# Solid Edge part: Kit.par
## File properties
Author: bmolnar
Last saved by: bmolnar
Revision: 78
Sűrűség: 0,000 kg/m^3
Pontosság: 0,990
Username: bmolnar
Dokumentum tartalom típus: 0
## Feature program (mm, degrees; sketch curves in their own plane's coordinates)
base feature "unnamed BaseFeature 1"
sketch for "unnamed Hole 1" plane through (44.5, 44.5, -94.5) normal (0, 0, -1) x-axis (-1, 0, 0)
  hole centre (0, 0) bore radius 4.188
hole "unnamed Hole 1" through
sketch for "unnamed Hole 2" plane through (44.5, 44.5, -94.5) normal (0, 0, -1) x-axis (-1, 0, 0)
  hole centre (89, 0) bore radius 4.188
hole "unnamed Hole 2" through
sketch for "unnamed Hole 3" plane through (44.5, 44.5, -94.5) normal (0, 0, -1) x-axis (-1, 0, 0)
  hole centre (89, -89) bore radius 4.188
hole "unnamed Hole 3" through
sketch for "unnamed Hole 4" plane through (44.5, 44.5, -94.5) normal (0, 0, -1) x-axis (-1, 0, 0)
  hole centre (0, -89) bore radius 4.188
hole "unnamed Hole 4" through
pattern "unnamed Pattern 1" of "unnamed Hole 1", "unnamed Hole 2", "unnamed Hole 3", "unnamed Hole 4"
sketch for "Furat_6" plane through (56.65, 0, -134.65) normal (-1, 0, 0) x-axis (0, 1, 0)
  hole centre (-0.0009, -47.65) bore radius 4.283
  dimension (linear) = 0.0009
hole "Furat_6" nominal diameter 9.728 finite  ThreadDepth = 12 mm
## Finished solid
Body 1: solid body, 320 faces, 792 edges, 492 vertices.
  Faces by surface: plane 145, cylinder 82, swept 56, cone 25, torus 11, spline 1
  Edges by curve: line 446, circle 180, spline 136, ellipse 28, curve on surface 2
Bounding box of the edges (mm; curved faces can reach further): 113.300 x 113.300 x 19.500, from (-56.65, -56.65, -97.5) to (56.65, 56.65, -78).
Cylindrical faces by radius (mm): R0.2 x48, R0.2006 x2, R0.2007 x2, R4.188 x4, R4.283 x1, R6.35 x4, R6.55 x4, R6.75 x4, R12.8 x1, R13.45 x1, R14 x1, R14.9 x1, R15 x1, R51.85 x8
Conical faces (half-angle, radius in mm at the cone's reference point): 0.5 deg R12.25 x4, 0.5 deg R35 x2, 3 deg R14.95 x1, 7 deg R14.2695 x1, 14 deg R12.65 x1, 14 deg R13.057 x1, 17 deg R12.65 x1, 23 deg R13.4211 x1, 42.5 deg R12.637 x1, 45 deg R4.185 x4, 45 deg R4.985 x4, 45 deg R13.6 x1, 84 deg R13.012 x1, 85 deg R14.6625 x1, 87 deg R12.7157 x1
Toroidal faces (ring radius, tube radius in mm): R6.05 r0.3 x2, R6.15 r0.2 x6, R13.4008 r0.225 x1, R13.8914 r0.325 x1, R14.7 r0.2 x1
Planar faces by outward normal: +x 17, +y 14, +z 2, -x 14, -y 16, -z 19, oblique 63
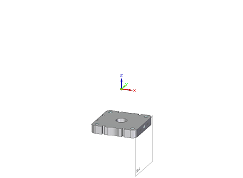
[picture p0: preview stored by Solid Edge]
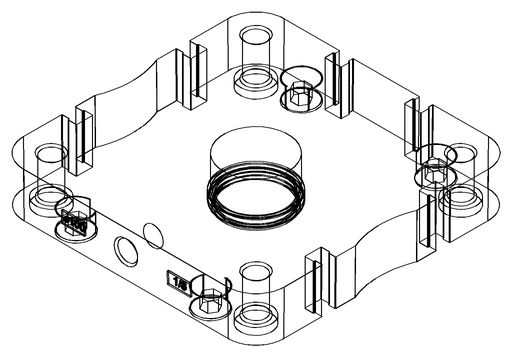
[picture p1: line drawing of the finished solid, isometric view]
